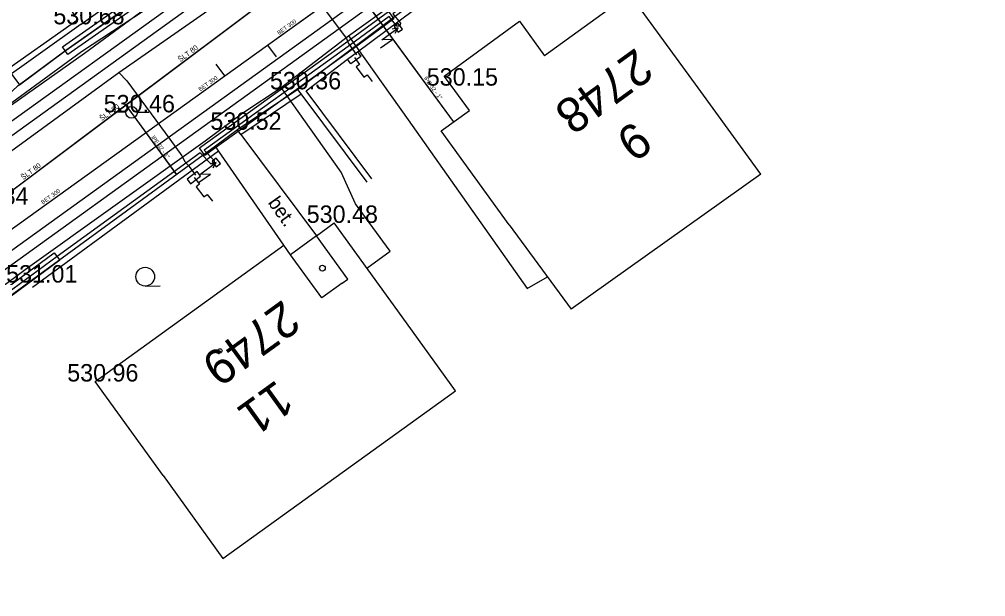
# Model space of a CAD drawing. Extents: x -668867 to -667827, y -1131943 to -1131019.
# Drawn here: x -668733.24 to -668691.62, y -1131416.31 to -1131391.45 of the extents above; entities that cross this region are included whole.
import ezdxf

# ---------------------------------------------------------------- set-up
doc = ezdxf.new("R2010")
doc.units = 0
for name, color, linetype in [('G_Bod_tecka', 7, 'Continuous'), ('G_Bod_vyska', 7, 'Continuous'), ('G_Budovy-znacky', 7, 'Continuous'), ('G_Budovy_Objekty', 7, 'Continuous'), ('G_Budovy_vstupy', 7, 'Continuous'), ('G_Cesty_Schody', 7, 'Continuous'), ('G_Cisla_orientacni', 7, 'Continuous'), ('G_Cisla_popisna', 7, 'Continuous'), ('G_Plochy_zpevnene', 7, 'Continuous'), ('G_Ploty', 7, 'Continuous'), ('G_Ploty_vstupy', 7, 'Continuous'), ('G_Popisy_povrchu', 7, 'Continuous'), ('G_Site-Rozvadece', 7, 'Continuous'), ('G_Site-vodovod', 7, 'Continuous'), ('G_Z_CHRANICKA-TEPLOVOD_kotovane', 7, 'Continuous'), ('G_Z_ELsilove_podz_kotovane', 7, 'Continuous'), ('G_Z_KANAL_podz_kotovane', 7, 'Continuous'), ('G_Z_PLYNY_podz_geodeticky', 7, 'Continuous'), ('G_Z_SPOJE_podz_geodeticky', 7, 'Continuous'), ('G_Z_SPOJE_podz_kotovane', 7, 'Continuous'), ('G_Z_SPOJE_podz_priblizne', 7, 'Continuous'), ('G_Z_VODA_podz_kotovane', 7, 'Continuous'), ('G_Zelen-Znacky', 7, 'Continuous'), ('Vrstva 10', 7, 'Continuous'), ('Vrstva 13', 7, 'Continuous'), ('Vrstva 17', 7, 'Continuous'), ('Vrstva 25', 7, 'Continuous'), ('Vrstva 26', 7, 'Continuous'), ('Vrstva 3', 7, 'Continuous'), ('Vrstva 4', 7, 'Continuous'), ('Vrstva 6', 7, 'Continuous')]:
    doc.layers.add(name, color=color, linetype=linetype)

msp = doc.modelspace()

# ---------------------------------------------------------------- linework, layer by layer
at = {"layer": 'G_Bod_tecka'}
for p, q in [((-668730.58, -1131391.66), (-668730.58, -1131391.66)), ((-668714.65, -1131394.3), (-668714.65, -1131394.3)), ((-668721.25, -1131394.46), (-668721.25, -1131394.46)), ((-668728.41, -1131395.45), (-668728.41, -1131395.45)), ((-668723.84, -1131396.2), (-668723.84, -1131396.2)), ((-668719.68, -1131400.21), (-668719.68, -1131400.21)), ((-668732.83, -1131402.78), (-668732.83, -1131402.78)), ((-668729.98, -1131407.04), (-668729.98, -1131407.04))]:
    msp.add_line(p, q, dxfattribs=at)
at = {"layer": 'G_Budovy-znacky'}
for centre, radius in [((-668709.66, -1131395.65), 0.0875), ((-668720.19, -1131402.16), 0.125), ((-668724.6, -1131405.72), 0.0875)]:
    msp.add_circle(centre, radius, dxfattribs=at)
at = {"layer": 'G_Budovy_Objekty'}
for p, q in [((-668704.01, -1131394.4), (-668706.95, -1131390.35)), ((-668714.94, -1131393.89), (-668711.7, -1131391.53)), ((-668711.7, -1131391.53), (-668710.62, -1131393.02)), ((-668714.65, -1131394.3), (-668714.94, -1131393.89)), ((-668713.86, -1131395.37), (-668714.65, -1131394.3)), ((-668701.3, -1131398.11), (-668704.01, -1131394.4)), ((-668715.08, -1131396.25), (-668713.86, -1131395.37)), ((-668712.14, -1131400.3), (-668715.08, -1131396.25)), ((-668701.3, -1131398.11), (-668709.48, -1131403.93)), ((-668720.45, -1131400.77), (-668719.68, -1131400.21)), ((-668716.75, -1131404.26), (-668719.68, -1131400.21)), ((-668712.14, -1131400.3), (-668709.48, -1131403.93)), ((-668720.45, -1131400.77), (-668721.56, -1131401.58)), ((-668719.1, -1131402.63), (-668720.45, -1131400.77)), ((-668729.98, -1131407.04), (-668721.85, -1131401.17)), ((-668721.56, -1131401.58), (-668721.85, -1131401.17)), ((-668720.21, -1131403.44), (-668721.56, -1131401.58)), ((-668719.34, -1131402.81), (-668719.1, -1131402.63)), ((-668714.46, -1131407.44), (-668716.75, -1131404.26)), ((-668727.05, -1131411.09), (-668729.98, -1131407.04)), ((-668724.48, -1131414.66), (-668714.46, -1131407.44)), ((-668727.05, -1131411.09), (-668724.48, -1131414.66))]:
    msp.add_line(p, q, dxfattribs=at)
msp.add_lwpolyline([(-668706.95, -1131390.35), (-668710.62, -1131393.02)], dxfattribs=at)
at = {"layer": 'G_Budovy_vstupy'}
msp.add_line((-668719.34, -1131402.81), (-668720.21, -1131403.44), dxfattribs=at)
at = {"layer": 'G_Cesty_Schody'}
for p, q in [((-668715.28, -1131383.29), (-668757.59, -1131413.74)), ((-668740.12, -1131406.11), (-668713.87, -1131387.19))]:
    msp.add_line(p, q, dxfattribs=at)
at = {"layer": 'G_Plochy_zpevnene'}
for p, q in [((-668715.57, -1131382.88), (-668757.89, -1131413.33)), ((-668739.83, -1131406.51), (-668713.58, -1131387.59)), ((-668733.62, -1131387.38), (-668730.73, -1131391.46)), ((-668723.7, -1131396.41), (-668720.45, -1131400.77)), ((-668721.85, -1131401.17), (-668724.66, -1131397.11))]:
    msp.add_line(p, q, dxfattribs=at)
at = {"layer": 'G_Ploty'}
for p, q in [((-668716.42, -1131390.85), (-668721.25, -1131394.46)), ((-668730.73, -1131391.46), (-668738.46, -1131396.93)), ((-668730.58, -1131391.66), (-668738.32, -1131397.14)), ((-668721.25, -1131394.46), (-668723.84, -1131396.2)), ((-668723.7, -1131396.41), (-668721.1, -1131394.66)), ((-668721.1, -1131394.66), (-668721.25, -1131394.46)), ((-668718.26, -1131398.46), (-668721.1, -1131394.66)), ((-668718.06, -1131398.32), (-668720.89, -1131394.52)), ((-668723.7, -1131396.41), (-668723.84, -1131396.2)), ((-668724.8, -1131396.91), (-668732.83, -1131402.78)), ((-668724.66, -1131397.11), (-668724.8, -1131396.91)), ((-668732.68, -1131402.98), (-668724.66, -1131397.11))]:
    msp.add_line(p, q, dxfattribs=at)
msp.add_lwpolyline([(-668720.89, -1131394.52), (-668719.11, -1131393.16), (-668718.68, -1131392.84), (-668716.27, -1131391.05)], dxfattribs=at)
at = {"layer": 'G_Ploty_vstupy'}
for p, q in [((-668730.58, -1131391.66), (-668727.24, -1131389.24)), ((-668723.84, -1131396.2), (-668724.8, -1131396.91)), ((-668732.83, -1131402.78), (-668735.79, -1131404.92))]:
    msp.add_line(p, q, dxfattribs=at)
at = {"layer": 'G_Site-Rozvadece'}
for p, q in [((-668717.627, -1131392.326), (-668716.92, -1131391.81)), ((-668716.92, -1131391.81), (-668717.183, -1131391.866)), ((-668717.053, -1131392.043), (-668716.92, -1131391.81)), ((-668717.682, -1131392.676), (-668717.176, -1131392.307)), ((-668717.176, -1131392.307), (-668717.627, -1131392.326)), ((-668725.467, -1131398.126), (-668724.76, -1131397.61)), ((-668724.76, -1131397.61), (-668725.023, -1131397.666)), ((-668724.893, -1131397.843), (-668724.76, -1131397.61)), ((-668725.522, -1131398.476), (-668725.016, -1131398.107)), ((-668725.016, -1131398.107), (-668725.467, -1131398.126))]:
    msp.add_line(p, q, dxfattribs=at)
for points in [[(-668716.92, -1131391.63), (-668717.1, -1131391.76), (-668716.92, -1131392), (-668716.74, -1131391.87)], [(-668724.76, -1131397.42), (-668724.94, -1131397.55), (-668724.76, -1131397.79), (-668724.58, -1131397.66)]]:
    msp.add_lwpolyline(points, close=True, dxfattribs=at)
for points in [[(-668718.68, -1131392.84), (-668718.53, -1131393.04), (-668718.96, -1131393.36), (-668719.11, -1131393.16)], [(-668718.81, -1131393.09), (-668718.591, -1131393.385), (-668718.738, -1131393.495), (-668718.408, -1131393.937), (-668718.261, -1131393.829), (-668718.04, -1131394.124)], [(-668725.59, -1131398), (-668726.02, -1131398.33), (-668725.87, -1131398.53), (-668725.44, -1131398.2), (-668725.59, -1131398)], [(-668725.71, -1131398.25), (-668725.487, -1131398.543), (-668725.632, -1131398.654), (-668725.296, -1131399.092), (-668725.15, -1131398.982), (-668724.925, -1131399.273)]]:
    msp.add_lwpolyline(points, dxfattribs=at)
at = {"layer": 'G_Site-vodovod'}
for p, q in [((-668728.66, -1131395.45), (-668729.16, -1131395.45)), ((-668728.16, -1131395.45), (-668727.66, -1131395.45))]:
    msp.add_line(p, q, dxfattribs=at)
msp.add_circle((-668728.41, -1131395.45), 0.25, dxfattribs=at)
at = {"layer": 'G_Z_CHRANICKA-TEPLOVOD_kotovane'}
for points in [[(-668731.385, -1131392.636), (-668725.837, -1131388.745), (-668725.396, -1131388.324), (-668724.553, -1131387.745), (-668724.327, -1131388.075), (-668725.144, -1131388.636), (-668725.583, -1131389.055), (-668731.156, -1131392.963)], [(-668717.348, -1131391.109), (-668717.112, -1131391.431), (-668718.861, -1131392.71), (-668725.253, -1131397.302), (-668725.487, -1131396.978), (-668719.097, -1131392.388)], [(-668737.829, -1131405.979), (-668731.738, -1131401.498), (-668731.501, -1131401.821), (-668737.592, -1131406.302)]]:
    msp.add_lwpolyline(points, close=True, dxfattribs=at)
at = {"layer": 'G_Z_ELsilove_podz_kotovane'}
for points in [[(-668733.816, -1131393.496), (-668733.23, -1131394.27), (-668731.27, -1131392.8), (-668725.71, -1131388.9), (-668725.27, -1131388.48), (-668724.44, -1131387.91), (-668723.34, -1131387.17), (-668710.851, -1131378.01), (-668711.308, -1131377.153), (-668711.26, -1131377.03), (-668711.132, -1131377.059), (-668710.679, -1131377.909), (-668709.97, -1131377.59), (-668699.401, -1131369.78), (-668699.806, -1131369.114), (-668700.114, -1131369.284), (-668700.26, -1131369.25), (-668700.21, -1131369.108), (-668699.734, -1131368.846), (-668699.239, -1131369.66), (-668694.09, -1131365.85), (-668693.32, -1131365.32), (-668678.7, -1131354.88)], [(-668688.53, -1131370.65), (-668693.68, -1131374.48), (-668694.845, -1131375.226), (-668694.456, -1131375.684), (-668694.479, -1131375.81), (-668694.608, -1131375.814), (-668695.011, -1131375.339), (-668701.78, -1131380.24), (-668705.67, -1131382.78), (-668712.54, -1131387.84), (-668717.149, -1131391.211), (-668716.824, -1131391.613), (-668716.849, -1131391.74), (-668716.98, -1131391.739), (-668717.311, -1131391.329), (-668718.98, -1131392.55), (-668725.288, -1131397.081), (-668724.854, -1131397.523), (-668724.85, -1131397.669), (-668724.996, -1131397.663), (-668725.452, -1131397.199), (-668731.62, -1131401.66), (-668737.627, -1131406.079)], [(-668761.242, -1131414.294), (-668758.43, -1131412.13), (-668758.21, -1131412), (-668758.21, -1131411.81), (-668758.19, -1131411.82), (-668758, -1131411.87), (-668757.46, -1131411.55), (-668748.36, -1131405.23), (-668745.77, -1131403.32), (-668745.4, -1131403.07), (-668741.67, -1131400.37), (-668741.88, -1131399.87), (-668741.89, -1131399.85), (-668741.49, -1131400.23), (-668733.81, -1131394.78), (-668733.29, -1131394.3), (-668731.24, -1131392.77), (-668725.68, -1131388.86), (-668725.4, -1131388.62), (-668725.61, -1131388.18), (-668725.61, -1131388.17), (-668725.24, -1131388.44), (-668724.41, -1131387.87), (-668723.31, -1131387.13)]]:
    msp.add_lwpolyline(points, dxfattribs=at)
at = {"layer": 'G_Z_KANAL_podz_kotovane'}
for p, q in [((-668722.55, -1131392.56), (-668722.18, -1131393.06)), ((-668724.39, -1131393.88), (-668724.77, -1131393.37))]:
    msp.add_line(p, q, dxfattribs=at)
msp.add_lwpolyline([(-668736.72, -1131402.73), (-668724.39, -1131393.88), (-668722.55, -1131392.56), (-668710.43, -1131383.87), (-668709.28, -1131383.04), (-668709.09, -1131382.9), (-668707.24, -1131381.57)], dxfattribs=at)
at = {"layer": 'G_Z_PLYNY_podz_geodeticky'}
for points in [[(-668733.62, -1131397.14), (-668728.96, -1131393.74), (-668721.77, -1131388.71), (-668720.25, -1131387.59), (-668715.23, -1131384.07), (-668712.64, -1131382.17), (-668712.18, -1131381.73), (-668705.29, -1131376.66), (-668701.28, -1131373.74), (-668698.48, -1131371.86), (-668693.74, -1131368.27), (-668688.53, -1131364.56)], [(-668721.77, -1131388.71), (-668721.62, -1131388.95), (-668719.64, -1131391.63), (-668719.15, -1131392.27), (-668719.07, -1131392.48), (-668718.72, -1131392.97)], [(-668728.96, -1131393.74), (-668728.62, -1131394.1), (-668726.76, -1131396.61), (-668726.25, -1131397.32), (-668726.12, -1131397.57), (-668725.97, -1131397.73), (-668725.66, -1131398.15)]]:
    msp.add_lwpolyline(points, dxfattribs=at)
at = {"layer": 'G_Z_SPOJE_podz_geodeticky'}
for points in [[(-668719.06, -1131392.16), (-668716.98, -1131390.66), (-668715.7, -1131389.78), (-668709.14, -1131385.18), (-668705.92, -1131382.93), (-668705.82, -1131382.6), (-668695.22, -1131375.13)], [(-668725.54, -1131389.31), (-668730.44, -1131392.92), (-668733.82, -1131395.31)], [(-668761.136, -1131414.404), (-668760.97, -1131414.27), (-668743.52, -1131401.83), (-668739.36, -1131399.26), (-668730.57, -1131392.83), (-668727.43, -1131390.78)], [(-668721.97, -1131394.38), (-668719.06, -1131392.16)], [(-668719.06, -1131392.16), (-668716.5, -1131395.78), (-668711.37, -1131403.04), (-668710.49, -1131402.54)], [(-668740.61, -1131407.88), (-668739.55, -1131407.08), (-668738.13, -1131406.01), (-668736.29, -1131404.67), (-668732.99, -1131402.22), (-668725.24, -1131396.68), (-668723.62, -1131395.47), (-668721.97, -1131394.38)], [(-668718.27, -1131402.16), (-668717.27, -1131401.43), (-668718.77, -1131399.39), (-668719.38, -1131398.03), (-668721.97, -1131394.38)]]:
    msp.add_lwpolyline(points, dxfattribs=at)
at = {"layer": 'G_Z_SPOJE_podz_kotovane'}
for points in [[(-668719.06, -1131392.16), (-668716.98, -1131390.66), (-668715.7, -1131389.78), (-668709.14, -1131385.18), (-668705.92, -1131382.93), (-668705.82, -1131382.6), (-668695.22, -1131375.13)], [(-668721.97, -1131394.38), (-668719.06, -1131392.16)], [(-668719.06, -1131392.16), (-668716.5, -1131395.78), (-668711.37, -1131403.04), (-668710.49, -1131402.54)], [(-668740.61, -1131407.88), (-668739.55, -1131407.08), (-668738.13, -1131406.01), (-668736.29, -1131404.67), (-668732.99, -1131402.22), (-668725.24, -1131396.68), (-668723.62, -1131395.47), (-668721.97, -1131394.38)], [(-668718.27, -1131402.16), (-668717.27, -1131401.43), (-668718.77, -1131399.39), (-668719.38, -1131398.03), (-668721.97, -1131394.38)]]:
    msp.add_lwpolyline(points, dxfattribs=at)
at = {"layer": 'G_Z_SPOJE_podz_priblizne'}
for points in [[(-668719.06, -1131392.16), (-668716.98, -1131390.66), (-668715.7, -1131389.78), (-668709.14, -1131385.18), (-668705.92, -1131382.93), (-668705.82, -1131382.6), (-668695.22, -1131375.13)], [(-668761.136, -1131414.404), (-668760.97, -1131414.27), (-668743.52, -1131401.83), (-668739.36, -1131399.26), (-668730.57, -1131392.83), (-668727.43, -1131390.78)], [(-668721.97, -1131394.38), (-668719.06, -1131392.16)], [(-668719.06, -1131392.16), (-668716.5, -1131395.78), (-668711.37, -1131403.04), (-668710.49, -1131402.54)], [(-668740.61, -1131407.88), (-668739.55, -1131407.08), (-668738.13, -1131406.01), (-668736.29, -1131404.67), (-668732.99, -1131402.22), (-668725.24, -1131396.68), (-668723.62, -1131395.47), (-668721.97, -1131394.38)], [(-668718.27, -1131402.16), (-668717.27, -1131401.43), (-668718.77, -1131399.39), (-668719.38, -1131398.03), (-668721.97, -1131394.38)]]:
    msp.add_lwpolyline(points, dxfattribs=at)
at = {"layer": 'G_Z_VODA_podz_kotovane'}
for points in [[(-668612.84, -1131311.89), (-668613.52, -1131312.39), (-668639.15, -1131330.75), (-668643.74, -1131334.04), (-668659.28, -1131345.16), (-668663.57, -1131348.23), (-668667.68, -1131351.59), (-668680.32, -1131360.39), (-668682.77, -1131361.98), (-668694.38, -1131370.3), (-668700.33, -1131374.56), (-668716.2, -1131385.93), (-668719.87, -1131388.55), (-668728.66, -1131395.15), (-668734.59, -1131399.59), (-668743.8, -1131406.5), (-668743.96, -1131406.62), (-668747.09, -1131408.97), (-668758.727, -1131416.908)], [(-668719.87, -1131388.55), (-668719.82, -1131388.63), (-668718.81, -1131390.04), (-668714.56, -1131395.84)], [(-668728.66, -1131395.15), (-668728.43, -1131395.46), (-668726.48, -1131398.13)]]:
    msp.add_lwpolyline(points, dxfattribs=at)
at = {"layer": 'G_Zelen-Znacky'}
msp.add_line((-668727.822, -1131402.93), (-668727.172, -1131402.927), dxfattribs=at)
msp.add_circle((-668727.822, -1131402.527), 0.403, dxfattribs=at)
at = {"layer": 'Vrstva 10'}
msp.add_lwpolyline([(-668736.723, -1131402.729), (-668724.39, -1131393.881), (-668722.554, -1131392.563), (-668710.431, -1131383.866), (-668709.277, -1131383.038), (-668709.09, -1131382.904), (-668707.238, -1131381.575)], dxfattribs=at)
at = {"layer": 'Vrstva 13'}
for p, q in [((-668722.554, -1131392.563), (-668722.181, -1131393.062)), ((-668724.39, -1131393.881), (-668724.772, -1131393.37))]:
    msp.add_line(p, q, dxfattribs=at)
at = {"layer": 'Vrstva 17'}
for p, q in [((-668731.24, -1131392.77), (-668725.68, -1131388.86)), ((-668733.29, -1131394.3), (-668731.24, -1131392.77))]:
    msp.add_line(p, q, dxfattribs=at)
at = {"layer": 'Vrstva 25'}
msp.add_lwpolyline([(-668719.869, -1131388.555), (-668719.819, -1131388.625), (-668718.808, -1131390.036), (-668714.557, -1131395.842)], dxfattribs=at)
at = {"layer": 'Vrstva 26'}
for points in [[(-668612.843, -1131311.885), (-668613.516, -1131312.393), (-668639.148, -1131330.746), (-668643.745, -1131334.037), (-668659.276, -1131345.158), (-668663.568, -1131348.231), (-668667.684, -1131351.593), (-668680.32, -1131360.39), (-668682.771, -1131361.982), (-668694.383, -1131370.3), (-668700.33, -1131374.561), (-668716.198, -1131385.926), (-668719.869, -1131388.555), (-668728.661, -1131395.148), (-668734.589, -1131399.593), (-668743.804, -1131406.503), (-668743.957, -1131406.618), (-668747.094, -1131408.971), (-668758.727, -1131416.908)], [(-668728.661, -1131395.148), (-668728.431, -1131395.463), (-668726.478, -1131398.135)]]:
    msp.add_lwpolyline(points, dxfattribs=at)
at = {"layer": 'Vrstva 6'}
msp.add_line((-668728.431, -1131395.463), (-668728.431, -1131395.463), dxfattribs=at)

# ---------------------------------------------------------------- texts
at = {"layer": 'G_Bod_vyska'}
for s, p in [('530.68', (-668731.779, -1131391.66)), ('530.15', (-668715.694, -1131394.3)), ('530.36', (-668722.449, -1131394.46)), ('530.46', (-668729.609, -1131395.45)), ('530.52', (-668725.016, -1131396.2)), ('530.84', (-668735.916, -1131399.43)), ('530.48', (-668720.866, -1131400.21)), ('531.01', (-668733.812, -1131402.78)), ('530.96', (-668731.181, -1131407.04))]:
    msp.add_text(s, height=0.75, dxfattribs=at).set_placement(p)
at = {"layer": 'G_Cisla_orientacni'}
for s, rotation, p in [('9', 215.9784, (-668706.74, -1131395.771)), ('11', 215.814, (-668722.148, -1131406.93))]:
    msp.add_text(s, height=1.5, rotation=rotation, dxfattribs=at).set_placement(p)
at = {"layer": 'G_Cisla_popisna'}
for s, p in [('2748', (-668706.681, -1131392.638)), ('2749', (-668721.886, -1131403.485))]:
    msp.add_text(s, height=1.5, rotation=215.9784, dxfattribs=at).set_placement(p)
at = {"layer": 'G_Popisy_povrchu'}
msp.add_text('bet.', height=0.6, rotation=305.2449, dxfattribs=at).set_placement((-668722.56, -1131399.341))
at = {"layer": 'Vrstva 3'}
for rotation, p in [(35.6946, (-668722.059, -1131392.121)), (35.6746, (-668725.45, -1131394.555)), (35.627, (-668732.232, -1131399.42))]:
    msp.add_text('BET 300', height=0.1755, rotation=rotation, dxfattribs=at).set_placement(p)
at = {"layer": 'Vrstva 4'}
for s, height, rotation, p in [('ŠLT 80', 0.2194, 36.8699, (-668726.306, -1131393.294)), ('lPE 32 - 1"', 0.17551, 306.1281, (-668715.833, -1131393.987)), ('ŠLT 80', 0.2194, 36.8699, (-668729.69, -1131395.832)), ('lPE 32 - 1"', 0.17551, 306.1953, (-668727.571, -1131396.534)), ('ŠLT 80', 0.2194, 36.8699, (-668733.073, -1131398.369))]:
    msp.add_text(s, height=height, rotation=rotation, dxfattribs=at).set_placement(p)

doc.saveas('drawing.dxf')
